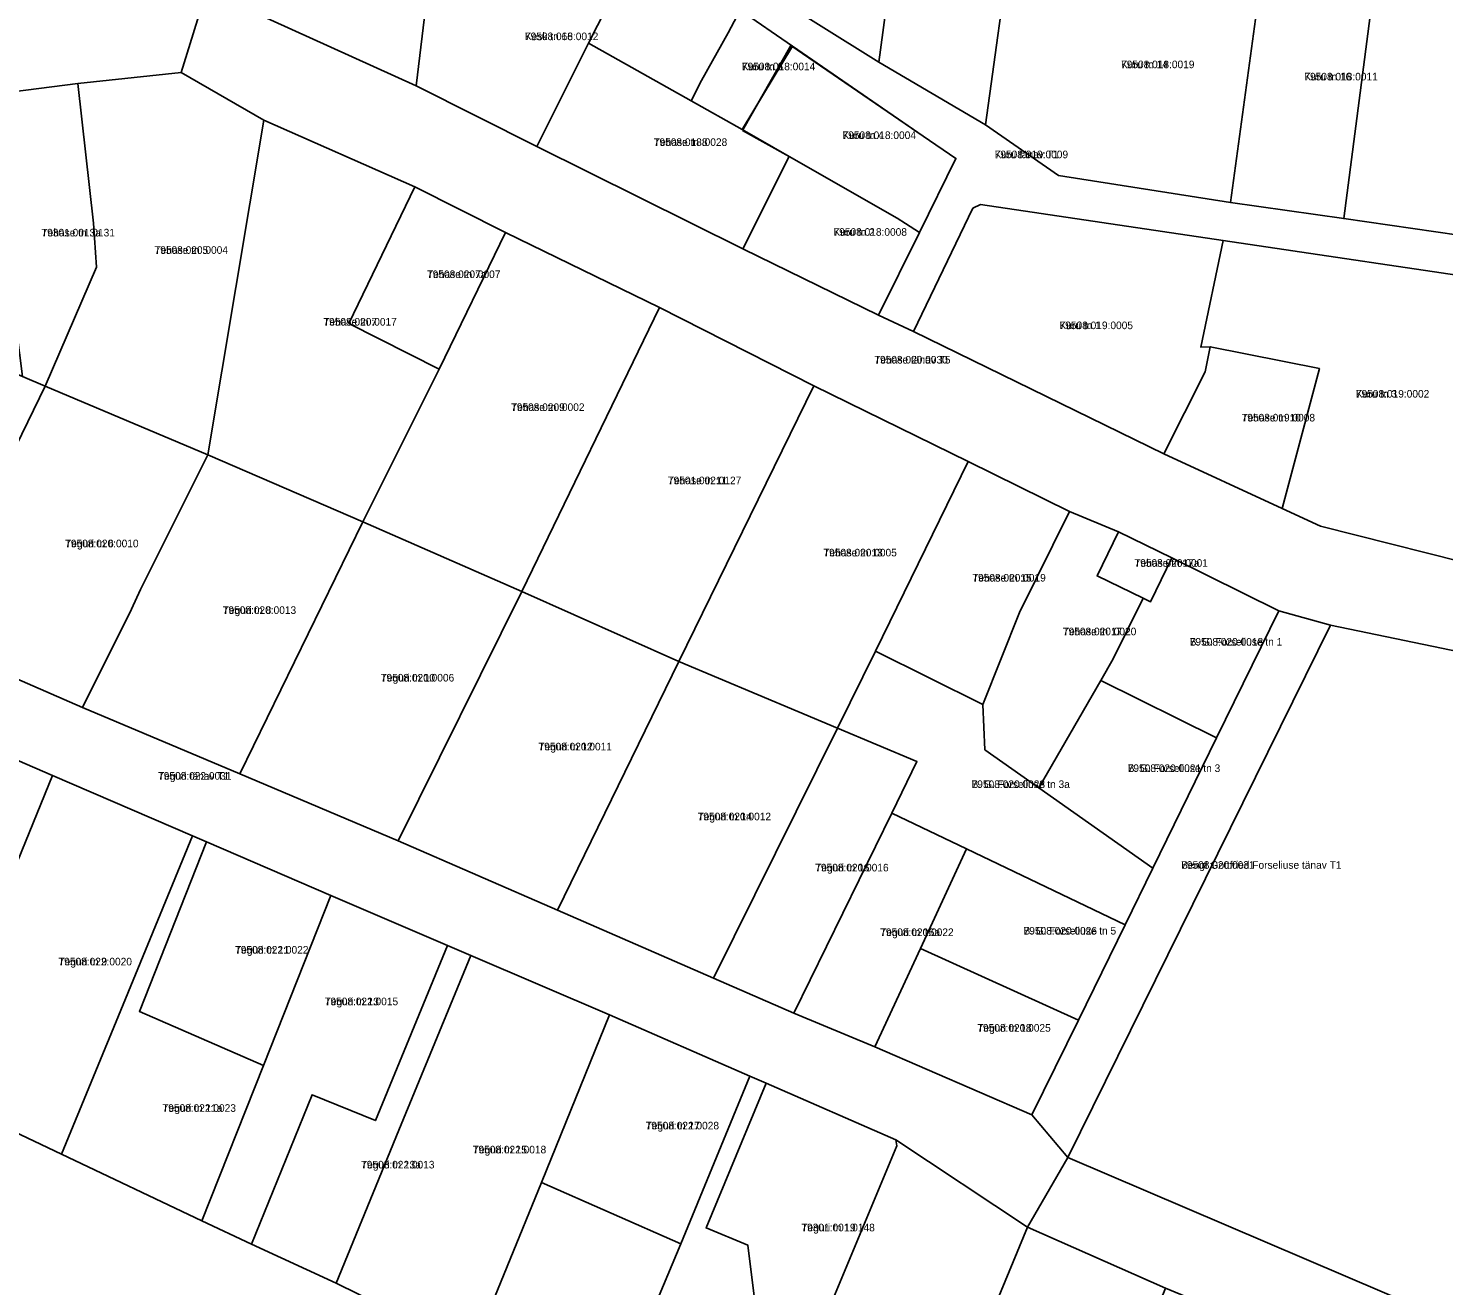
# Model space of a CAD drawing. Extents: x 643847 to 663718, y 6468443 to 6482775.
# Drawn here: x 659394.5 to 659674.1, y 6472008.9 to 6472257.2 of the extents above; entities that cross this region are included whole.
import ezdxf

# ---------------------------------------------------------------- set-up
doc = ezdxf.new("R2010")
doc.units = 0
for name, color, linetype in [('L_AADRESS', 7, 'Continuous'), ('PIIR', 7, 'Continuous'), ('TUNNUS', 7, 'Continuous')]:
    doc.layers.add(name, color=color, linetype=linetype)

msp = doc.modelspace()

# ---------------------------------------------------------------- linework, layer by layer
at = {"layer": 'PIIR'}
for points in [[(659535.14, 6472260.85), (659532.76, 6472256.38), (659527.5, 6472246.94), (659525.47, 6472242.9), (659505.16, 6472254.32), (659514.1, 6472271.95), (659523.81, 6472291.25), (659530.43, 6472304.34), (659538.43, 6472298.16), (659541.96, 6472295.15), (659541.3, 6472294.04), (659536.1, 6472284.67), (659535.02, 6472282.59), (659535.26, 6472282.56), (659527.78, 6472268.63), (659531.28, 6472266.7), (659531.2, 6472266.55), (659533.87, 6472265.08), (659536.58, 6472263.52)], [(659562.51, 6472250.54), (659538.14, 6472265.81), (659552.23, 6472287.79), (659566.09, 6472277.05)], [(659474.86, 6472277.02), (659514.1, 6472271.95), (659505.16, 6472254.32), (659494.93, 6472233.9), (659471.12, 6472245.9)], [(659562.51, 6472250.54), (659566.09, 6472277.05), (659588.81, 6472275.87), (659583.59, 6472238.17)], [(659598, 6472228.2), (659583.59, 6472238.17), (659588.81, 6472275.87), (659590.98, 6472275.73), (659613.26, 6472274.7), (659638.88, 6472273.59), (659631.96, 6472222.84)], [(659631.96, 6472222.84), (659638.88, 6472273.59), (659644.87, 6472273.24), (659661.17, 6472272.31), (659660.4, 6472266.34), (659654.34, 6472219.65)], [(659660.4, 6472266.34), (659729.58, 6472263.07), (659729.34, 6472257.89), (659740.12, 6472258.65), (659740.34, 6472253.68), (659743.05, 6472214.52), (659723.03, 6472213.12), (659709.72, 6472212.93), (659706.96, 6472239.75), (659680.55, 6472240.41), (659677.08, 6472216.4), (659654.34, 6472219.65)], [(659313.65, 6472235), (659271.02, 6472230.17), (659253.87, 6472227.9), (659248.18, 6472224.99), (659245.75, 6472241.64), (659281.86, 6472245.92), (659300.93, 6472248.34), (659307.63, 6472249.17), (659358.02, 6472255.39), (659381.7, 6472258.42), (659411.12, 6472261.87), (659429.74, 6472264.68), (659424.69, 6472248.5), (659404.26, 6472246.32), (659386.23, 6472244.03), (659361.56, 6472240.9), (659339.8, 6472238.07)], [(659527.5, 6472246.94), (659532.76, 6472256.38), (659535.14, 6472260.85), (659545.46, 6472253.74), (659535.5, 6472237.25), (659525.47, 6472242.9)], [(659535.64, 6472213.7), (659494.93, 6472233.9), (659505.16, 6472254.32), (659525.47, 6472242.9), (659535.5, 6472237.25), (659544.81, 6472231.91)], [(659535.59, 6472237.05), (659545.11, 6472253.85), (659571.29, 6472235.95), (659577.75, 6472231.53), (659570.53, 6472216.91), (659567.81, 6472218.67), (659566.14, 6472219.74), (659544.8, 6472231.91)], [(659386.23, 6472244.03), (659404.26, 6472246.32), (659407.41, 6472218.74), (659408.01, 6472210.07), (659397.86, 6472186.55), (659393.39, 6472188.48)], [(659424.69, 6472248.5), (659441.04, 6472239.1), (659429.96, 6472173.04), (659397.86, 6472186.55), (659408.01, 6472210.07), (659407.41, 6472218.74), (659404.26, 6472246.32)], [(659470.88, 6472225.91), (659457.8, 6472198.95), (659475.65, 6472189.94), (659460.61, 6472159.79), (659429.96, 6472173.04), (659441.04, 6472239.1)], [(659562.48, 6472200.62), (659535.64, 6472213.7), (659544.81, 6472231.91), (659566.14, 6472219.74), (659567.81, 6472218.67), (659570.53, 6472216.91)], [(659488.75, 6472216.93), (659475.65, 6472189.94), (659457.8, 6472198.95), (659470.88, 6472225.91)], [(659581.1, 6472221.7), (659582.59, 6472222.46), (659630.53, 6472215.36), (659626.13, 6472194.27), (659627.98, 6472194.34), (659626.96, 6472189.43), (659618.8, 6472173.19), (659569.34, 6472197.35)], [(659475.65, 6472189.94), (659488.75, 6472216.93), (659519.16, 6472202.11), (659492, 6472146.03), (659460.61, 6472159.79)], [(659687.36, 6472206.9), (659686.07, 6472175.83), (659684.7, 6472150.13), (659649.79, 6472158.92), (659642.19, 6472162.41), (659649.56, 6472190.03), (659627.98, 6472194.34), (659626.13, 6472194.27), (659630.53, 6472215.36)], [(659492, 6472146.03), (659519.16, 6472202.11), (659549.7, 6472186.62), (659522.99, 6472132.2)], [(659373.61, 6472136.89), (659342.79, 6472149.87), (659367.08, 6472199.89), (659393.39, 6472188.48), (659397.86, 6472186.55)], [(659618.8, 6472173.19), (659626.96, 6472189.43), (659627.98, 6472194.34), (659649.56, 6472190.03), (659642.19, 6472162.41)], [(659373.61, 6472136.89), (659397.86, 6472186.55), (659429.96, 6472173.04), (659416.69, 6472146.38), (659414.87, 6472142.5), (659405.23, 6472123.1)], [(659554.38, 6472119.01), (659522.99, 6472132.2), (659549.7, 6472186.62), (659580.14, 6472171.67), (659561.83, 6472134.24)], [(659405.23, 6472123.1), (659414.87, 6472142.5), (659416.69, 6472146.38), (659429.96, 6472173.04), (659460.61, 6472159.79), (659436.27, 6472110)], [(659600.16, 6472161.8), (659590.3, 6472141.88), (659583.05, 6472123.7), (659561.83, 6472134.24), (659580.14, 6472171.67)], [(659492, 6472146.03), (659467.59, 6472096.78), (659436.27, 6472110), (659460.61, 6472159.79)], [(659609.88, 6472157.83), (659605.64, 6472149.09), (659614.71, 6472144.67), (659608.83, 6472132.75), (659606.35, 6472128.46), (659594.11, 6472107.27), (659583.48, 6472114.76), (659583.05, 6472123.7), (659590.3, 6472141.88), (659600.16, 6472161.8)], [(659620.38, 6472152.64), (659616.15, 6472143.97), (659614.71, 6472144.67), (659605.64, 6472149.09), (659609.88, 6472157.83)], [(659641.5, 6472142.21), (659629.24, 6472117.15), (659606.35, 6472128.46), (659608.83, 6472132.75), (659614.71, 6472144.67), (659616.15, 6472143.97), (659620.38, 6472152.64)], [(659467.59, 6472096.78), (659492, 6472146.03), (659522.99, 6472132.2), (659499.06, 6472083.07)], [(659629.24, 6472117.15), (659641.5, 6472142.21), (659651.73, 6472139.4), (659599.84, 6472034.26), (659592.76, 6472042.64), (659601.93, 6472061.37), (659611.15, 6472080.17), (659616.64, 6472091.41)], [(659799.34, 6471963.32), (659763.93, 6471964.14), (659599.84, 6472034.26), (659651.73, 6472139.4), (659726.75, 6472123.86), (659792.58, 6472117.39)], [(659611.15, 6472080.17), (659579.84, 6472095.17), (659565.06, 6472102.24), (659570.05, 6472112.43), (659554.38, 6472119.01), (659561.83, 6472134.24), (659583.05, 6472123.7), (659583.48, 6472114.76), (659594.11, 6472107.27), (659616.64, 6472091.41)], [(659499.06, 6472083.07), (659522.99, 6472132.2), (659554.38, 6472119.01), (659529.86, 6472069.65)], [(659616.64, 6472091.41), (659594.11, 6472107.27), (659606.35, 6472128.46), (659629.24, 6472117.15)], [(659399.29, 6472109.7), (659374.03, 6472047.72), (659346.82, 6472060.36), (659371.74, 6472121.58)], [(659529.86, 6472069.65), (659554.38, 6472119.01), (659570.05, 6472112.43), (659565.06, 6472102.24), (659545.73, 6472062.74)], [(659426.93, 6472097.78), (659413.25, 6472064.48), (659401.08, 6472034.89), (659374.03, 6472047.72), (659399.29, 6472109.7)], [(659545.73, 6472062.74), (659565.06, 6472102.24), (659579.84, 6472095.17), (659570.74, 6472075.53), (659561.74, 6472056.11)], [(659426.93, 6472097.78), (659429.69, 6472096.59), (659416.45, 6472063.09), (659440.95, 6472052.41), (659428.81, 6472021.73), (659401.08, 6472034.89), (659413.25, 6472064.48)], [(659429.69, 6472096.59), (659454.24, 6472086), (659440.95, 6472052.41), (659416.45, 6472063.09)], [(659611.15, 6472080.17), (659601.93, 6472061.37), (659570.74, 6472075.53), (659579.84, 6472095.17)], [(659477.31, 6472076.13), (659463.08, 6472041.53), (659450.56, 6472046.63), (659438.58, 6472017.13), (659428.81, 6472021.73), (659440.95, 6472052.41), (659454.24, 6472086)], [(659481.91, 6472074.16), (659467.72, 6472039.65), (659455.29, 6472009.42), (659438.58, 6472017.13), (659450.56, 6472046.63), (659463.08, 6472041.53), (659477.31, 6472076.13)], [(659601.93, 6472061.37), (659592.76, 6472042.64), (659561.74, 6472056.11), (659570.74, 6472075.53)], [(659509.33, 6472062.42), (659495.85, 6472029.33), (659482.31, 6471996.12), (659455.29, 6472009.42), (659467.72, 6472039.65), (659481.91, 6472074.16)], [(659509.33, 6472062.42), (659537.05, 6472050.32), (659523.41, 6472017.21), (659495.85, 6472029.33)], [(659523.41, 6472017.21), (659537.05, 6472050.32), (659540.28, 6472048.92), (659528.4, 6472020.35), (659536.64, 6472016.91), (659539.12, 6471996.77), (659547.98, 6471993.1), (659538.55, 6471970.38), (659509.38, 6471983.74)], [(659528.4, 6472020.35), (659540.28, 6472048.92), (659565.89, 6472037.76), (659566.04, 6472036.53), (659547.98, 6471993.1), (659539.12, 6471996.77), (659536.64, 6472016.91)], [(659591.88, 6472020.51), (659565.73, 6471957.31), (659538.55, 6471970.38), (659547.98, 6471993.1), (659566.04, 6472036.53), (659565.89, 6472037.76)], [(659619.13, 6472008.43), (659591.88, 6472020.51), (659599.84, 6472034.26), (659763.93, 6471964.14), (659799.34, 6471963.32), (659804.07, 6471929.38), (659803.01, 6471929.86), (659779.72, 6471940.09), (659757.36, 6471949.31), (659743.61, 6471955.05), (659729.7, 6471960.87), (659726.05, 6471962.34), (659701.79, 6471972.5), (659673.86, 6471984.99), (659646.99, 6471996.58), (659642.46, 6471998.69), (659633.62, 6472002.42)], [(659495.85, 6472029.33), (659523.41, 6472017.21), (659509.38, 6471983.74), (659482.31, 6471996.12)], [(659619.13, 6472008.43), (659593.24, 6471944.68), (659565.73, 6471957.31), (659591.88, 6472020.51)]]:
    msp.add_lwpolyline(points, close=True, dxfattribs=at)
for points in [[(659474.86, 6472277.02), (659471.12, 6472245.9), (659429.74, 6472264.68)], [(659538.14, 6472265.81), (659562.51, 6472250.54), (659583.59, 6472238.17), (659598, 6472228.2), (659631.96, 6472222.84), (659654.34, 6472219.65), (659677.08, 6472216.4)], [(659726.75, 6472123.86), (659651.73, 6472139.4), (659641.5, 6472142.21), (659620.38, 6472152.64), (659609.88, 6472157.83), (659600.16, 6472161.8), (659580.14, 6472171.67), (659549.7, 6472186.62), (659519.16, 6472202.11), (659488.75, 6472216.93), (659470.88, 6472225.91), (659441.04, 6472239.1), (659424.69, 6472248.5), (659429.74, 6472264.68), (659471.12, 6472245.9), (659494.93, 6472233.9), (659535.64, 6472213.7), (659562.48, 6472200.62), (659569.34, 6472197.35), (659618.8, 6472173.19), (659642.19, 6472162.41), (659649.79, 6472158.92), (659684.7, 6472150.13)], [(659687.36, 6472206.9), (659630.53, 6472215.36), (659582.59, 6472222.46), (659581.1, 6472221.7), (659569.34, 6472197.35), (659562.48, 6472200.62), (659570.53, 6472216.91), (659577.75, 6472231.53), (659571.29, 6472235.95), (659545.46, 6472253.74), (659535.14, 6472260.85)], [(659373.61, 6472136.89), (659405.23, 6472123.1), (659436.27, 6472110), (659467.59, 6472096.78), (659499.06, 6472083.07), (659529.86, 6472069.65), (659545.73, 6472062.74), (659561.74, 6472056.11), (659592.76, 6472042.64), (659599.84, 6472034.26), (659591.88, 6472020.51), (659565.89, 6472037.76), (659540.28, 6472048.92), (659537.05, 6472050.32), (659509.33, 6472062.42), (659481.91, 6472074.16), (659477.31, 6472076.13), (659454.24, 6472086), (659429.69, 6472096.59), (659426.93, 6472097.78), (659399.29, 6472109.7), (659371.74, 6472121.58)], [(659374.03, 6472047.72), (659401.08, 6472034.89), (659428.81, 6472021.73), (659438.58, 6472017.13), (659455.29, 6472009.42), (659482.31, 6471996.12), (659509.38, 6471983.74), (659538.55, 6471970.38), (659565.73, 6471957.31), (659593.24, 6471944.68), (659619.7, 6471931.97), (659646.78, 6471919.6), (659674.5, 6471906.35), (659701.71, 6471893.43), (659715.46, 6471887.27), (659729.12, 6471881.02), (659808.32, 6471844.79), (659812.93, 6471842.65), (659817.75, 6471799.3), (659780.42, 6471814.89), (659659.13, 6471870.87), (659658.51, 6471876.15), (659456.43, 6471970.64), (659371.65, 6472005.08)]]:
    msp.add_lwpolyline(points, dxfattribs=at)

# ---------------------------------------------------------------- texts
at = {"layer": 'L_AADRESS'}
for s, p in [('Kesk tn 66', (659492.61, 6472254.9)), ('Kuru tn 6', (659535.46, 6472248.95)), ('Kuru tn 14', (659610.36, 6472249.36)), ('Kuru tn 16', (659646.57, 6472246.95)), ('Tehase tn 8', (659518.07, 6472234.01)), ('Kuru tn 4', (659555.35, 6472235.38)), ('Kuru tänav T1', (659585.4, 6472231.58)), ('Tehase tn 3a', (659397.12, 6472216.14)), ('Kuru tn 2', (659553.57, 6472216.27)), ('Tehase tn 5', (659419.45, 6472212.7)), ('Tehase tn 7a', (659473.27, 6472207.92)), ('Tehase tn 7', (659452.8, 6472198.53)), ('Kuru tn 1', (659598.22, 6472197.83)), ('Tehase tänav T5', (659561.63, 6472191.04)), ('Kuru tn 3', (659656.75, 6472184.31)), ('Tehase tn 9', (659489.88, 6472181.67)), ('Tehase tn 10', (659634.18, 6472179.6)), ('Tehase tn 11', (659520.85, 6472167.2)), ('Teguri tn 6', (659401.79, 6472154.75)), ('Tehase tn 13', (659551.57, 6472152.95)), ('Tehase tn 17a', (659613.02, 6472150.9)), ('Tehase tn 15', (659580.99, 6472147.98)), ('Teguri tn 8', (659432.92, 6472141.59)), ('Tehase tn 17', (659598.88, 6472137.37)), ('B. G. Forseliuse tn 1', (659623.93, 6472135.33)), ('Teguri tn 10', (659464.14, 6472128.24)), ('Teguri tn 12', (659495.29, 6472114.64)), ('B. G. Forseliuse tn 3', (659611.68, 6472110.37)), ('Teguri tänav T1', (659420.14, 6472108.85)), ('B. G. Forseliuse tn 3a', (659580.85, 6472107.21)), ('Teguri tn 14', (659526.72, 6472100.83)), ('Teguri tn 16', (659549.95, 6472090.74)), ('Bengt Gottfried Forseliuse tänav T1', (659622.24, 6472091.26)), ('Teguri tn 16a', (659562.79, 6472077.98)), ('B. G. Forseliuse tn 5', (659591.11, 6472078.27)), ('Teguri tn 11', (659435.35, 6472074.5)), ('Teguri tn 9', (659400.48, 6472072.18)), ('Teguri tn 13', (659453.06, 6472064.31)), ('Teguri tn 18', (659581.97, 6472059.09)), ('Teguri tn 11a', (659421.02, 6472043.26)), ('Teguri tn 17', (659516.45, 6472039.79)), ('Teguri tn 15', (659482.31, 6472035.05)), ('Teguri tn 13a', (659460.24, 6472032.08)), ('Teguri tn 19', (659547.22, 6472019.66))]:
    msp.add_text(s, height=1.5, dxfattribs=at).set_placement(p)
at = {"layer": 'TUNNUS'}
for s, p in [('79508:018:0012', (659492.61, 6472254.9)), ('79508:018:0014', (659535.46, 6472248.95)), ('79508:018:0019', (659610.36, 6472249.36)), ('79508:018:0011', (659646.57, 6472246.95)), ('79508:018:0028', (659518.07, 6472234.01)), ('79508:018:0004', (659555.35, 6472235.38)), ('79508:019:0009', (659585.4, 6472231.58)), ('79301:001:0131', (659397.12, 6472216.14)), ('79508:018:0008', (659553.57, 6472216.27)), ('79508:020:0004', (659419.45, 6472212.7)), ('79508:020:0007', (659473.27, 6472207.92)), ('79508:020:0017', (659452.8, 6472198.53)), ('79508:019:0005', (659598.22, 6472197.83)), ('79508:020:0030', (659561.63, 6472191.04)), ('79508:019:0002', (659656.75, 6472184.31)), ('79508:020:0002', (659489.88, 6472181.67)), ('79508:019:0008', (659634.18, 6472179.6)), ('79501:002:0127', (659520.85, 6472167.2)), ('79508:020:0010', (659401.79, 6472154.75)), ('79508:020:0005', (659551.57, 6472152.95)), ('79508:020:0001', (659613.02, 6472150.9)), ('79508:020:0019', (659580.99, 6472147.98)), ('79508:020:0013', (659432.92, 6472141.59)), ('79508:020:0020', (659598.88, 6472137.37)), ('79508:020:0018', (659623.93, 6472135.33)), ('79508:020:0006', (659464.14, 6472128.24)), ('79508:020:0011', (659495.29, 6472114.64)), ('79508:020:0021', (659611.68, 6472110.37)), ('79508:022:0031', (659420.14, 6472108.85)), ('79508:020:0023', (659580.85, 6472107.21)), ('79508:020:0012', (659526.72, 6472100.83)), ('79508:020:0016', (659549.95, 6472090.74)), ('79508:020:0031', (659622.24, 6472091.26)), ('79508:020:0022', (659562.79, 6472077.98)), ('79508:020:0026', (659591.11, 6472078.27)), ('79508:022:0022', (659435.35, 6472074.5)), ('79508:022:0020', (659400.48, 6472072.18)), ('79508:022:0015', (659453.06, 6472064.31)), ('79508:020:0025', (659581.97, 6472059.09)), ('79508:022:0023', (659421.02, 6472043.26)), ('79508:022:0028', (659516.45, 6472039.79)), ('79508:022:0018', (659482.31, 6472035.05)), ('79508:022:0013', (659460.24, 6472032.08)), ('79301:001:0148', (659547.22, 6472019.66))]:
    msp.add_text(s, height=1.5, dxfattribs=at).set_placement(p)

doc.saveas('drawing.dxf')
